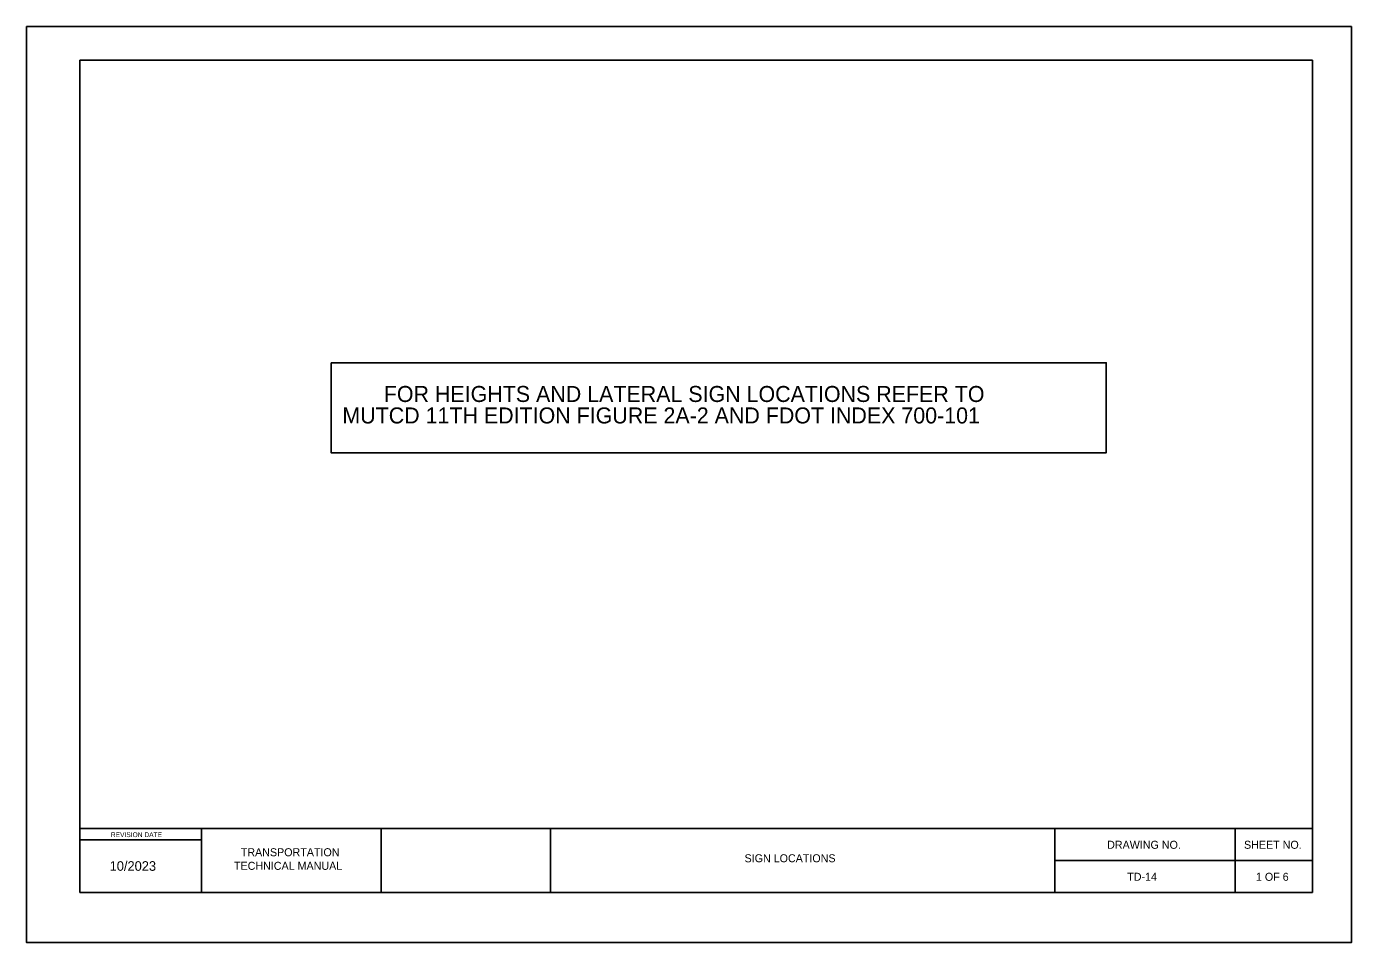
# Model space of a CAD drawing. Extents: x -14.6 to 39.7, y -12.4 to 25.1.
import ezdxf

# ---------------------------------------------------------------- set-up
doc = ezdxf.new("R2010")
doc.units = 0
for name, color, linetype in [('Default', 7, 'Continuous'), ('NonPlottingEle_dp', 7, 'Continuous'), ('SheetBorder_dp', 7, 'Continuous'), ('SheetLines_dp', 7, 'Continuous'), ('TextMinor', 7, 'Continuous')]:
    doc.layers.add(name, color=color, linetype=linetype)

msp = doc.modelspace()

# ---------------------------------------------------------------- linework, layer by layer
at = {"layer": 'Default'}
msp.add_lwpolyline([(-2.085, 11.359), (29.691, 11.359), (29.691, 7.669), (-2.085, 7.669)], close=True, dxfattribs=at)
at = {"layer": 'NonPlottingEle_dp'}
msp.add_lwpolyline([(38.12, 25.141), (-14.569, 25.141), (-14.569, -12.409), (39.74, -12.409), (39.74, 25.141)], close=True, dxfattribs=at)
at = {"layer": 'SheetBorder_dp'}
for p, q in [((-12.382, 23.76), (-12.382, -10.361)), ((-12.382, 23.76), (38.143, 23.76)), ((38.143, 23.76), (38.143, -10.361)), ((-12.382, -7.741), (38.143, -7.741)), ((-12.382, -10.361), (38.143, -10.361))]:
    msp.add_line(p, q, dxfattribs=at)
at = {"layer": 'SheetLines_dp'}
for p, q in [((-7.394, -7.736), (-7.394, -10.361)), ((-0.027, -7.736), (-0.027, -10.361)), ((6.912, -7.741), (6.912, -10.361)), ((27.582, -10.361), (27.582, -7.736)), ((34.972, -10.361), (34.972, -7.736)), ((-12.382, -8.196), (-7.394, -8.196)), ((27.582, -9.049), (38.143, -9.049))]:
    msp.add_line(p, q, dxfattribs=at)

# ---------------------------------------------------------------- texts
at = {"layer": 'TextMinor'}
for s, height, p in [('FOR HEIGHTS AND LATERAL SIGN LOCATIONS REFER TO ', 0.65617, (0.076, 9.749)), ('MUTCD 11TH EDITION FIGURE 2A-2 AND FDOT INDEX 700-101 ', 0.65617, (-1.623, 8.869)), ('REVISION DATE', 0.19685, (-11.112, -8.089)), ('TRANSPORTATION', 0.32808, (-5.786, -8.873)), ('DRAWING NO.', 0.32808, (29.724, -8.567)), ('SHEET NO.', 0.3281, (35.335, -8.567)), ('10/2023', 0.3937, (-11.162, -9.47)), ('TECHNICAL MANUAL', 0.32808, (-6.066, -9.43)), ('SIGN LOCATIONS', 0.32808, (14.862, -9.12)), ('TD-14', 0.3281, (30.548, -9.879)), ('1 OF 6 ', 0.3281, (35.824, -9.879))]:
    msp.add_text(s, height=height, dxfattribs=at).set_placement(p)

doc.saveas('drawing.dxf')
